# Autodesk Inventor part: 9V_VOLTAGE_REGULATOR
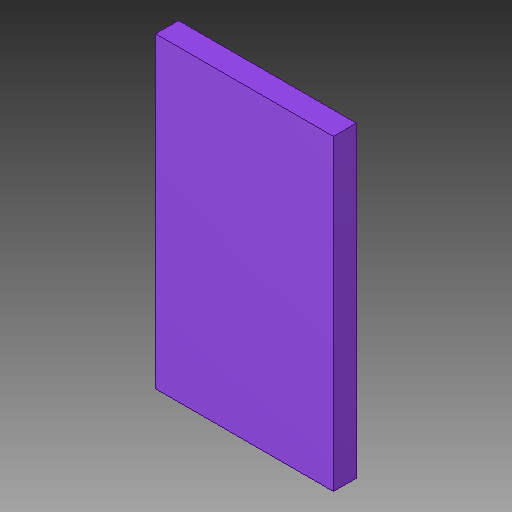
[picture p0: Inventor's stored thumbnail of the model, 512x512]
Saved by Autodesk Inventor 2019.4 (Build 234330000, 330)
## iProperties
Created: 2019-11
Part Number: 9V_VOLTAGE_REGULATOR
Material: Generic
Document SubType Name: Modeling
Designer: Willist
Density: 1 g/cm^3
Appearance: 9V_VOLTAGE_REGULATOR, 9V_VOLTAGE_REGULATOR
Author: Willist
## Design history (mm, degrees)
sketch "9V_VOLTAGE_REGULATOR, 9V_VOLTAGE_REGULATOR_59"
  geometry: L1 (-3.874, 10.795)-(3.874, 10.795); L2 (3.874, 10.795)-(3.874, -2.604); L3 (3.874, -2.604)-(-3.874, -2.604); L4 (-3.874, -2.604)-(-3.874, 10.795)
  constraints: 8 end point
extrude "Extrusion1" join sketch "9V_VOLTAGE_REGULATOR, 9V_VOLTAGE_REGULATOR_59" distance "d0" = 1; taper "d1" = 0 deg
body "Solid1"
